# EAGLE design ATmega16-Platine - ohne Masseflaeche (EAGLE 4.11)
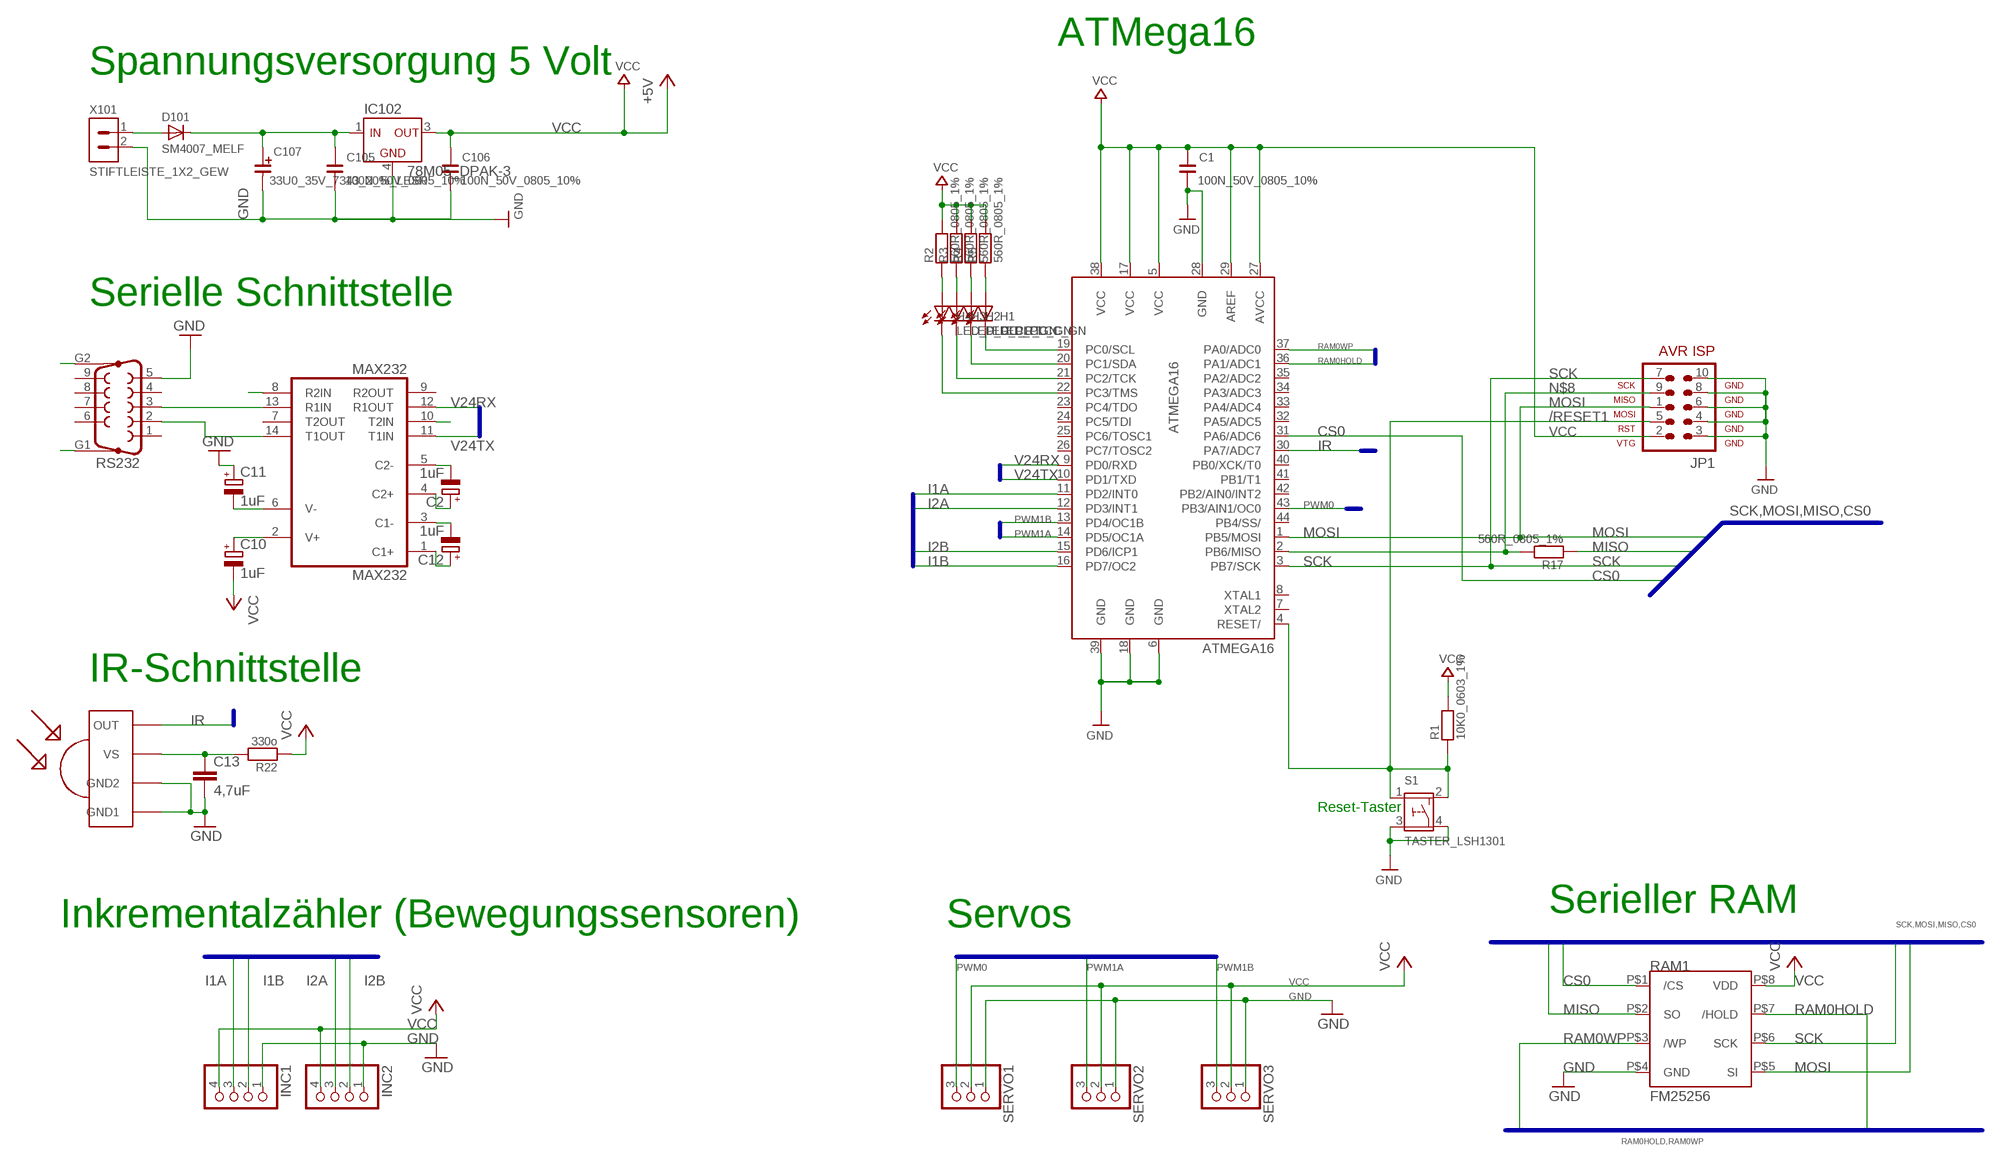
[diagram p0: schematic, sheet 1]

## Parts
ATMEGA16  ATMEGA16  [SQFP-S-10X10-44]
C1  100N_50V_0805_10%  [C0805]
C2  1uF  CPOL-EUE2.5-5  [E2,5-5]
C10  1uF  CPOL-EUE2.5-5  [E2,5-5]
C11  1uF  CPOL-EUE2.5-5  [E2,5-5]
C12  1uF  CPOL-EUE2.5-5  [E2,5-5]
C13  4,7uF  C-EU025-024X044  [C025-024X044]
C105  100N_50V_0805_10%  [C0805]
C106  100N_50V_0805_10%  [C0805]
C107  33U0_35V_7343_20%_LESR  [CT7343]
D101  SM4007_MELF  [MELF]
H1  LED_PLCC_GN  [PLCC2]
H2  LED_PLCC_GN  [PLCC2]
H3  LED_PLCC_GN  [PLCC2]
H4  LED_PLCC_RT  [PLCC2]
IC102  78M05_DPAK-3  [DPAK-3]
INC1  PINHD-1X4  [1X04]
INC2  PINHD-1X4  [1X04]
JP1  AVR-ISP-10  [AVR-ISP-10]
MAX232  MAX232  [DIL16]
R1  10K0_0603_1%  [R0603]
R2  560R_0805_1%  [R0805]
R3  560R_0805_1%  [R0805]
R4  560R_0805_1%  [R0805]
R5  560R_0805_1%  [R0805]
R17  560R_0805_1%  [R0805]
R22  330o  10K0_0603_1%  [R0603]
RAM1  FM25256  [EIAJ-SOIC-8]
RS232  F09HP  [F09HP]
S1  TASTER_LSH1301  [LSH1301]
SERVO1  PINHD-1X3  [1X03]
SERVO2  PINHD-1X3  [1X03]
SERVO3  PINHD-1X3  [1X03]
TSOP6236  TSOP6236  [TSOP62XX]
X101  STIFTLEISTE_1X2_GEW  [PFOSTENSTECKER_1X2_GEW]

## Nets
/RESET1: ATMEGA16.4(RESET/) JP1.5 R1.1 S1.1 S1.2
CS0: ATMEGA16.31(PA6/ADC6) RAM1.P$1(/CS)
GND: ATMEGA16.6(GND) ATMEGA16.18(GND) ATMEGA16.28(GND) ATMEGA16.39(GND) C1.2 C11.+ C13.2 C105.2 C106.2 C107.-(MINUS) IC102.4(GND) INC1.1 INC2.1 JP1.3 JP1.4 JP1.6 JP1.8 JP1.10 MAX232.8(R2IN) MAX232.10(T2IN) RAM1.P$4(GND) RS232.5 RS232.G1 RS232.G2 S1.3 S1.4 SERVO1.1 SERVO2.1 SERVO3.1 TSOP6236.GND1 TSOP6236.GND2 X101.2
I1A: ATMEGA16.11(PD2/INT0) INC1.3
I1B: ATMEGA16.16(PD7/OC2) INC1.2
I2A: ATMEGA16.12(PD3/INT1) INC2.3
I2B: ATMEGA16.15(PD6/ICP1) INC2.2
IR: ATMEGA16.30(PA7/ADC7) TSOP6236.OUT
MISO: R17.1 RAM1.P$2(SO)
MOSI: ATMEGA16.1(PB5/MOSI) JP1.1 RAM1.P$5(SI)
N$8: ATMEGA16.2(PB6/MISO) JP1.9 R17.2
N$9: D101.A X101.1
N$11: H1.A(A1) R5.1
N$12: C105.1 C107.+(PLUS) D101.C IC102.1(IN)
N$13: H2.A(A1) R4.1
N$19: H3.A(A1) R3.1
N$20: H4.A(A1) R2.1
N$21: ATMEGA16.19(PC0/SCL) H1.K
N$22: ATMEGA16.20(PC1/SDA) H2.K
N$23: ATMEGA16.21(PC2/TCK) H3.K
N$24: ATMEGA16.22(PC3/TMS) H4.K
N$29: C2.- MAX232.5(C2-)
N$30: C2.+ MAX232.4(C2+)
N$31: C12.- MAX232.3(C1-)
N$32: C12.+ MAX232.1(C1+)
N$33: C11.- MAX232.6(V-)
N$34: C10.+ MAX232.2(V+)
N$40: MAX232.14(T1OUT) RS232.2
N$41: MAX232.13(R1IN) RS232.3
N$49: C13.1 R22.2 TSOP6236.VS
PWM0: ATMEGA16.43(PB3/AIN1/OC0) SERVO1.3
PWM1A: ATMEGA16.14(PD5/OC1A) SERVO2.3
PWM1B: ATMEGA16.13(PD4/OC1B) SERVO3.3
RAM0HOLD: ATMEGA16.36(PA1/ADC1) RAM1.P$7(/HOLD)
RAM0WP: ATMEGA16.37(PA0/ADC0) RAM1.P$3(/WP)
SCK: ATMEGA16.3(PB7/SCK) JP1.7 RAM1.P$6(SCK)
V24RX: ATMEGA16.9(PD0/RXD) MAX232.12(R1OUT)
V24TX: ATMEGA16.10(PD1/TXD) MAX232.11(T1IN)
VCC: ATMEGA16.5(VCC) ATMEGA16.17(VCC) ATMEGA16.27(AVCC) ATMEGA16.29(AREF) ATMEGA16.38(VCC) C1.1 C10.- C106.1 IC102.3(OUT) INC1.4 INC2.4 JP1.2 R1.2 R2.2 R3.2 R4.2 R5.2 R22.1 RAM1.P$8(VDD) SERVO1.2 SERVO2.2 SERVO3.2 ; supply symbol labelled +5V
Unconnected: ATMEGA16.7(XTAL2) ATMEGA16.8(XTAL1) ATMEGA16.23(PC4/TDO) ATMEGA16.24(PC5/TDI) ATMEGA16.25(PC6/TOSC1) ATMEGA16.26(PC7/TOSC2) ATMEGA16.32(PA5/ADC5) ATMEGA16.33(PA4/ADC4) ATMEGA16.34(PA3/ADC3) ATMEGA16.35(PA2/ADC2) ATMEGA16.40(PB0/XCK/T0) ATMEGA16.41(PB1/T1) ATMEGA16.42(PB2/AIN0/INT2) ATMEGA16.44(PB4/SS/) MAX232.7(T2OUT) MAX232.9(R2OUT) RS232.1 RS232.4 RS232.6 RS232.7 RS232.8 RS232.9

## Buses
SCK,MOSI,MISO,CS0
IR
PWM0,PWM1A,PWM1B
V24RX,V24TX
I1A,I1B,I2A,I2B
RAM0HOLD,RAM0WP

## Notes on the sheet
- ATMega16
- Spannungsversorgung 5 Volt
- Serielle Schnittstelle
- IR-Schnittstelle
- Reset-Taster
- Servos
- Serieller RAM
- Inkrementalzähler (Bewegungssensoren)

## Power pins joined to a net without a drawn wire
GND: MAX232.15(GND)
VCC: MAX232.16(VCC)

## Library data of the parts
ATMEGA16 = IntegrierteSchaltkreise:ATMEGA16: xxxxxxxx
C1 C105 C106 = Kondensatoren:100N_50V_0805_10%: 10100000
C2 C10-C12 = rcl:CPOL-EU: POLARIZED CAPACITOR, European symbol
C13 = rcl:C-EU: CAPACITOR, European symbol
C107 = Kondensatoren:33U0_35V_7343_20%_LESR: 10100525
D101 = Diode:SM4007_MELF: 10300033
H1-H3 = LED:LED_PLCC_GN: 10800036
H4 = LED:LED_PLCC_RT: 10800053
IC102 = IntegrierteSchaltkreise:78M05_DPAK-3: 10500443
INC1 INC2 = pinhead:PINHD-1X4: PIN HEADER
JP1 = atmel_3:AVR-ISP-10: AVR ISP-10 Serial Programming Header
MAX232 = maxim:MAX232: RS232 TRANSEIVER
R1 R22 = Widerstände:10K0_0603_1%: 10000534
R2-R5 R17 = Widerstände:560R_0805_1%: 10000417
RAM1 = ramtron25xx:FM25256
RS232 = con-subd:F09HP: SUB-D
S1 = Schalter_Taster:TASTER_LSH1301: 11100014
SERVO1-SERVO3 = pinhead:PINHD-1X3: PIN HEADER
TSOP6236 = tsop_2:TSOP6236
X101 = Stecker_Klemmen:STIFTLEISTE_1X2_GEW: 20900248

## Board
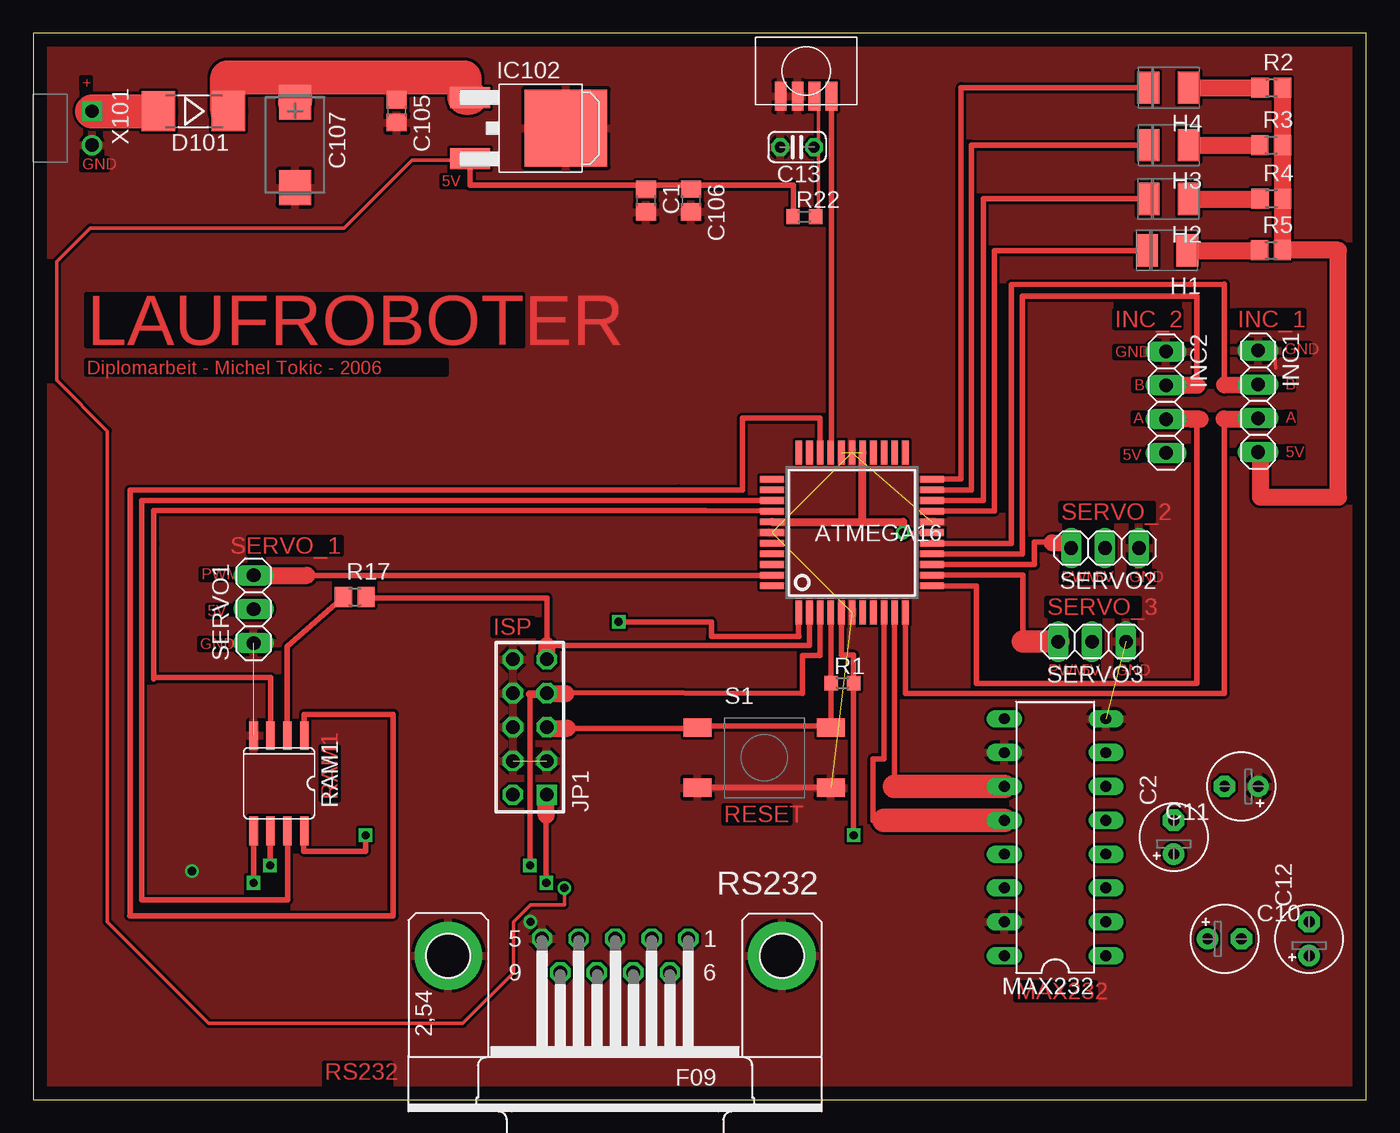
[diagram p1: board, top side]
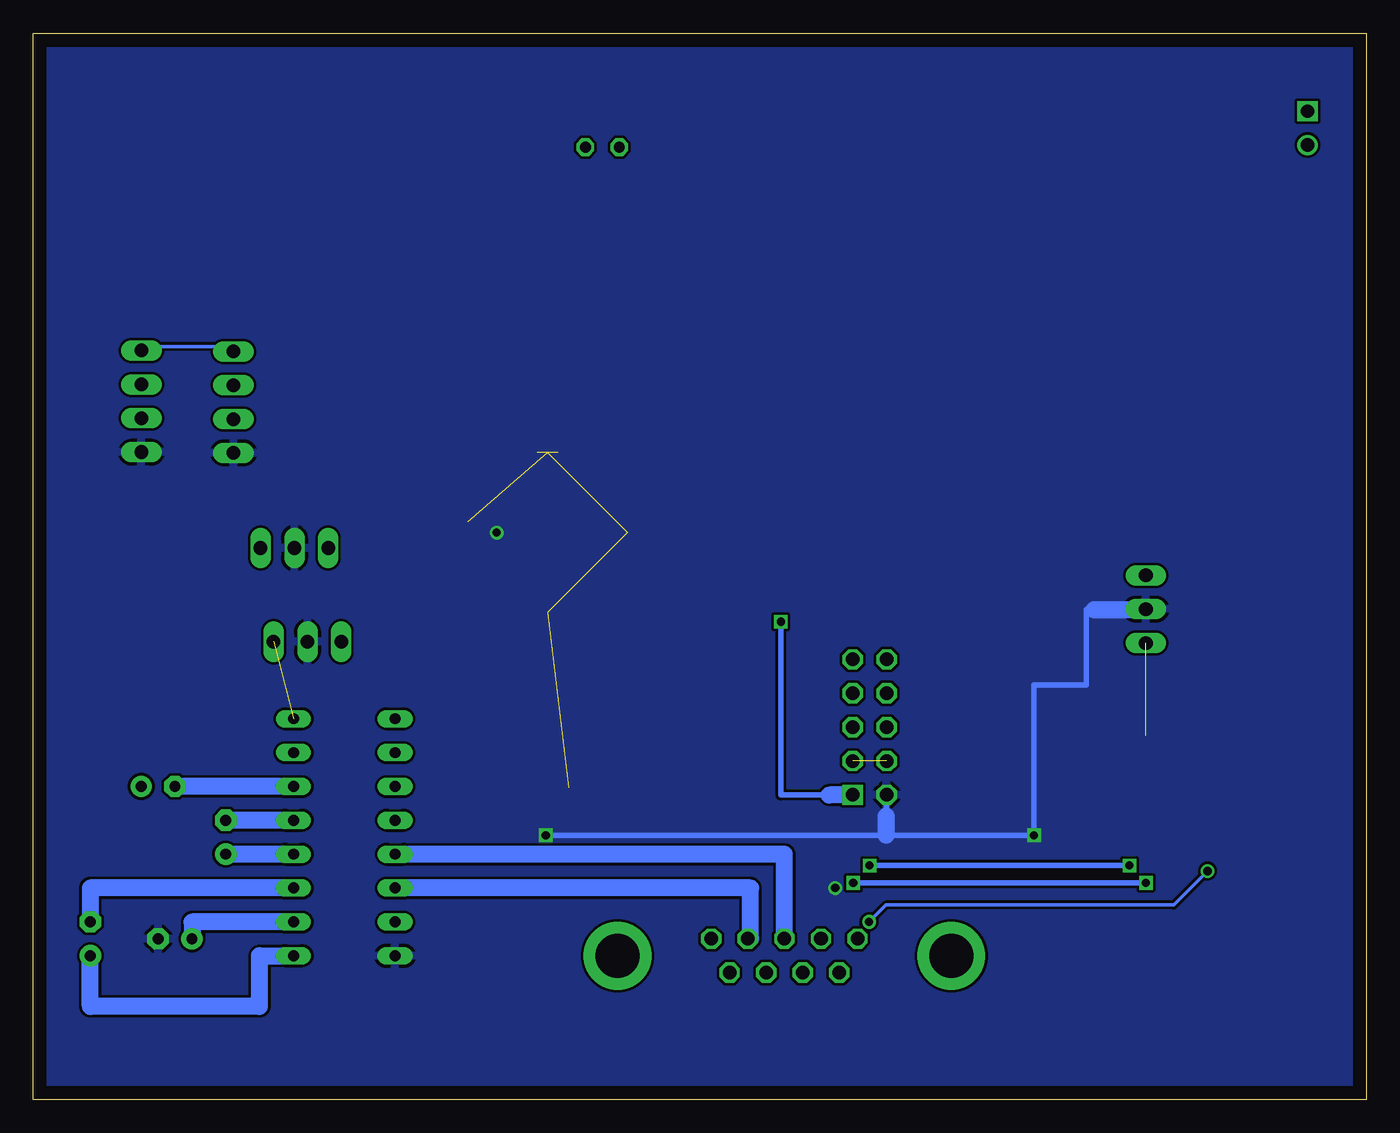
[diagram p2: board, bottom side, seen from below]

Size 100 x 80 mm. Coordinates in mm from the lower left corner, seen from the top.
Outline: 0,0 100,0 100,80 0,80 0,0
Copper layers (1*16): Top 0.035mm / dielectric 1.5mm / Bottom 0.035mm
Design rules "default": minimum track width 10mil, minimum drill 24mil, track to track 8mil, track to pad 8mil, pad to pad 8mil, via to via 8mil, smd to smd 8mil, copper to edge 40mil, drill to drill 8mil, minimum pad ring 10mil, minimum via ring 8mil, stop-mask expansion 4mil, vias tented up to drill 0mil, thermal gap 10mil

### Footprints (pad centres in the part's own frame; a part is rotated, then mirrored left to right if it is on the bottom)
SQFP-S-10X10-44 = smd 0.5 x 1.8: 1 -4,-6; 2 -3.2,-6; 3 -2.4,-6; 4 -1.6,-6; 5 -0.8,-6; 6 0,-6; 7 0.8,-6; 8 1.6,-6; 9 2.4,-6; 10 3.2,-6; 11 4,-6; 23 4,6; 24 3.2,6; 25 2.4,6; 26 1.6,6; 27 0.8,6; 28 0,6; 29 -0.8,6; 30 -1.6,6; 31 -2.4,6; 32 -3.2,6; 33 -4,6 | smd 1.8 x 0.5: 12 6,-4; 13 6,-3.2; 14 6,-2.4; 15 6,-1.6; 16 6,-0.8; 17 6,0; 18 6,0.8; 19 6,1.6; 20 6,2.4; 21 6,3.2; 22 6,4; 34 -6,4; 35 -6,3.2; 36 -6,2.4; 37 -6,1.6; 38 -6,0.8; 39 -6,0; 40 -6,-0.8; 41 -6,-1.6; 42 -6,-2.4; 43 -6,-3.2; 44 -6,-4
C0805 = smd 1.3 x 1.5: 1 -0.85,0; 2 0.85,0
E2,5-5 = drill 0.813 pad 1.6 round: + -1.27,0 | drill 0.813 pad 1.6 octagon: - 1.27,0
C025-024X044 = drill 0.813 octagon: 1 -1.27,0; 2 1.27,0
CT7343 = smd 2.6 x 2.4: + -3.2,0; - 3.2,0
MELF = smd 2.5 x 3: A 2.625,0; C -2.625,0
PLCC2 = smd 1.651 x 2.413: A 1.524,0; K -1.524,0
DPAK-3 = smd 3 x 1.6: 1 -7.18,2.286; 3 -7.18,-2.286 | smd 6.2 x 5.8: 4 0,0
1X04 = drill 1.016 long: 1 -3.81,0; 2 -1.27,0; 3 1.27,0; 4 3.81,0
AVR-ISP-10 = drill 1.016 square: 1 -5.08,-1.27 | drill 1.016 octagon: 2 -5.08,1.27; 3 -2.54,-1.27; 4 -2.54,1.27; 5 0,-1.27; 6 0,1.27; 7 2.54,-1.27; 8 2.54,1.27; 9 5.08,-1.27; 10 5.08,1.27
DIL16 = drill 0.813 long: 1 -8.89,-3.81; 2 -6.35,-3.81; 3 -3.81,-3.81; 4 -1.27,-3.81; 5 1.27,-3.81; 6 3.81,-3.81; 7 6.35,-3.81; 8 8.89,-3.81; 9 8.89,3.81; 10 6.35,3.81; 11 3.81,3.81; 12 1.27,3.81; 13 -1.27,3.81; 14 -3.81,3.81; 15 -6.35,3.81; 16 -8.89,3.81
R0603 = smd 1 x 1.1: 1 -0.85,0; 2 0.85,0
R0805 = smd 1.3 x 1.5: 1 -0.85,0; 2 0.85,0
EIAJ-SOIC-8 = smd 0.65 x 2.15: P$1 -1.905,-3.576; P$2 -0.635,-3.576; P$3 0.635,-3.576; P$4 1.905,-3.576; P$5 1.905,3.576; P$6 0.635,3.576; P$7 -0.635,3.576; P$8 -1.905,3.576
F09HP = drill 1.016 octagon: 1 -5.486,-1.27; 2 -2.743,-1.27; 3 0,-1.27; 4 2.743,-1.27; 5 5.486,-1.27; 6 -4.115,1.27; 7 -1.372,1.27; 8 1.372,1.27; 9 4.115,1.27 | drill 3.302 pad 5.08 round: G1 -12.522,0; G2 12.522,0
LSH1301 = smd 2.1 x 1.4: 1 -5,2.25; 2 5,2.25; 3 -5,-2.25; 4 5,-2.25
1X03 = drill 1.016 long: 1 -2.54,0; 2 0,0; 3 2.54,0
TSOP62XX = smd 0.889 x 2.184: GND1 -8.255,1.905; GND2 -6.985,1.905; OUT -4.445,1.905; VS -5.715,1.905
PFOSTENSTECKER_1X2_GEW = drill 1 square: 1 -1.27,0 | drill 1 round: 2 1.27,0

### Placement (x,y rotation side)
ATMEGA16  61.43,42.54 0 top
C1  45.97,67.45 270 top
C2  85.56,19.68 90 top
C10  89.37,12.06 0 top
C11  90.64,23.49 180 top
C12  95.72,12.06 90 top
C13  57.31,71.46 180 top
C105  27.26,74.16 270 top
C106  49.35,67.46 270 top
C107  19.64,71.62 270 top
D101  12.02,74.16 180 top
H1  85.05,63.71 0 top
H2  85.17,67.57 0 top
H3  85.18,71.61 0 top
H4  85.19,75.92 0 top
IC102  39.96,72.89 0 top
INC1  91.89,52.39 270 top
INC2  84.98,52.32 270 top
JP1  37.25,27.94 90 top
MAX232  76.67,19.68 90 top
R1  60.7,31.25 0 top
R2  92.89,75.92 0 top
R3  92.86,71.61 0 top
R4  92.9,67.61 0 top
R5  92.85,63.71 0 top
R17  24.12,37.7 0 top
R22  57.84,66.24 0 top
RAM1  18.43,23.73 180 top
RS232  43.65,10.79 180 top
S1  54.84,25.65 0 top
SERVO1  16.53,36.79 90 top
SERVO2  80.41,41.38 180 top
SERVO3  79.43,34.36 180 top
TSOP6236  64.33,73.37 0 top
X101  4.4,72.89 270 top

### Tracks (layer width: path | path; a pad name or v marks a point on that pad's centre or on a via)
/RESET1
  Top 0.406: ATMEGA16.4 59.83,31.25 R1.1 59.85,28.38 59.84,28.37 | 59.84,28.37 59.81,28.34 | 59.84,28.03 S1.2 | 59.84,28.03 59.84,28.37 | 38.48,27.9 38.46,27.9 | JP1.5 38.48,27.9 | 38.48,27.9 38.48,27.86 | 40.07,27.86 40.07,27.84 49.84,27.86 S1.1 49.84,28.03 59.84,28.03
  Top 1.27: 38.48,27.86 40.07,27.86
CS0
  Top 0.406: RAM1.P$1 20.33,28.89 26.99,28.89 26.99,13.79 7.21,13.79 7.26,13.83 7.26,45.72 48.44,45.73 53.2,45.73 53.2,51.12 59.02,51.12 ATMEGA16.31 | ATMEGA16.31 59.02,48.43 | ATMEGA16.31
GND  (via drill 0.61)  (7 unrouted)
  Top 0.254: INC1.1 93.18,56.51 93.18,55.24 93.22,54.89
  Top 0.406: S1.4 59.84,23.42 49.84,23.42 S1.3
  Bottom 0.254: INC1.1 90.64,56.51 85.56,56.51 INC2.1 | v37.3,13.33 36.03,14.6 14.44,14.6 v11.9,17.14
  pour Top: 0.47,79.64 99.48,79.64 99.48,0.41 0.58,0.41 0.58,79.31
I1A
  Top 0.406: ATMEGA16.11 65.44,30.46 89.35,30.46 89.35,51.07 | 92,51.08 92,51.07 INC1.3
  Top 1.27: 89.35,51.07 92,51.07
I1B
  Top 0.406: 89.37,53.61 89.37,61.17 73.37,61.14 73.37,43.39 73.4,43.39 73.4,41.73 67.16,41.73 67.16,41.74 | 67.16,41.74 67.16,41.78 | ATMEGA16.16 67.16,41.74
  Top 1.27: 89.37,53.61 INC1.2
I2A
  Top 0.406: ATMEGA16.12 70.77,38.54 70.77,31.22 87.28,31.22 87.28,51.04 | 86.91,51.04 87.52,51.05
  Top 1.27: 87.52,51.05 INC2.3 | 87.28,51.04 86.91,51.04
I2B
  Top 0.406: ATMEGA16.15 74.22,40.94 74.22,42.6 74.21,42.6 74.21,60.28 87.3,60.29 87.3,53.58 | 85.83,53.74 INC2.2
  Top 1.27: 85.83,53.69 85.83,53.74 85.91,53.58 87.3,53.58
IR
  Top 0.406: ATMEGA16.30 59.8,48.54 59.79,48.56 59.89,48.66 TSOP6236.OUT
MISO
  Top 0.406: 19.05,27.28 | RAM1.P$2 19.05,27.28 | R17.1 19.05,34.01 19.05,27.28
MOSI  (via drill 0.61)
  Top 0.406: RAM1.P$5 v16.52,16.26 | JP1.1 38.54,22.85 | JP1.1 | v38.49,16.26 38.48,21.33 | 38.48,22.85 JP1.1 | v43.92,35.85 50.87,35.85 50.87,34.73 57.45,34.73 57.41,34.77 57.41,36.52 ATMEGA16.1
  Top 1.27: 38.48,21.33 38.48,22.85
  Bottom 0.406: v16.52,16.26 v38.49,16.26 | JP1.1 | 40.28,22.85 40.28,22.86 43.92,22.85 v43.92,35.85
  Bottom 1.27: JP1.1 40.28,22.85
N$8
  Top 0.406: R17.2 24.92,37.65 38.54,37.65 38.54,33.03 38.53,33.03 JP1.9 | 38.53,34.07 58.24,34.07 ATMEGA16.2
  Top 1.27: JP1.9 38.53,34.07
N$9
  Top 2.54: 8.21,74.16 X101.1 D101.A
N$11
  Top 1.27: 91.78,63.72 | 91.78,63.72 R5.1 | H1.A 91.78,63.71 91.78,63.72
N$12
  Top 1.27: 27.26,76.7 C105.1
  Top 2.54: D101.C 14.56,74.16 14.56,76.7 19.64,76.7 | 19.64,76.7 19.64,75.43 | 19.64,76.7 C107.+ | IC102.1 32.34,75.17 32.34,76.7 27.26,76.7 19.64,76.7
N$13
  Top 1.27: R4.1 92.04,67.57 H2.A
N$19
  Top 1.27: R3.1 91.89,71.61 H3.A
N$20
  Top 1.27: 91.85,75.92 91.85,75.91 R2.1 | H4.A 91.85,75.92 | 91.85,75.92 91.85,75.93
N$21
  Top 0.406: ATMEGA16.19 72.1,44.14 72.1,63.68 83.29,63.68 83.29,63.71 | 83.29,63.71 83.29,63.72 | 83.29,63.71 H1.K
N$22
  Top 0.406: ATMEGA16.20 71.27,44.94 71.27,67.59 83.48,67.59 83.48,67.57 | 83.48,67.57 83.48,67.52 | 83.48,67.57 H2.K
N$23
  Top 0.406: ATMEGA16.21 70.36,45.74 70.36,71.61 83.44,71.61 | 83.44,71.61 | 83.44,71.61 H3.K
N$24
  Top 0.406: ATMEGA16.22 69.61,46.54 69.61,75.93 83.44,75.93 83.44,75.92 H4.K
N$29
  Bottom 1.27: MAX232.5 C2.-
N$30
  Bottom 1.27: MAX232.4 C2.+
N$31
  Bottom 1.27: MAX232.3 95.72,15.87 C12.-
N$32
  Bottom 1.27: MAX232.1 83.02,10.79 83.02,6.98 95.72,6.98 C12.+
N$33
  Bottom 1.27: MAX232.6 C11.-
N$34
  Bottom 1.27: MAX232.2 88.1,13.33 C10.+
N$40
  Bottom 1.27: MAX232.14 46.19,15.87 46.19,12.06 RS232.2
N$41
  Bottom 1.27: MAX232.13 43.65,18.41 RS232.3
N$49
  Top 0.254: 58.89,71.75 58.89,66.67 R22.2 | 58.89,71.75 58.89,74.29 TSOP6236.VS | 58.89,71.75 C13.1
PWM0
  Top 0.406: 55.3,39.33 55.31,39.34 ATMEGA16.43 | 55.3,39.33 | 55.3,39.33 55.22,39.33 55.21,39.34 55.2,39.33 20.54,39.33
  Top 1.27: SERVO1.3 20.54,39.33
PWM1A
  Top 0.254: SERVO2.3 77.94,41.27 77.94,41.78
  Top 0.406: ATMEGA16.14 75.12,40.14 75.12,41.82 75.11,41.82 75.12,41.83 76.39,41.84 76.44,41.76
  Top 1.27: 76.44,41.76 77.94,41.78 77.99,41.78
PWM1B
  Top 0.406: ATMEGA16.13 74.23,39.34 74.23,34.36
  Top 1.676: 74.23,34.36 SERVO3.3
RAM0HOLD
  Top 0.406: RAM1.P$7 19.09,20.13 19.09,14.99 8.12,14.99 8.12,44.94 49.39,44.94 49.28,44.94 55.21,44.94 | 55.21,44.94 55.21,44.99 | 55.21,44.94 ATMEGA16.36
RAM0WP
  Top 0.406: RAM1.P$3 17.81,27.31 17.81,31.67 9.05,31.67 | 9.05,31.67 9.02,31.67 | ATMEGA16.37 55.46,44.17 50.45,44.2 50.45,44.21 9.05,44.21 9.05,41.66 | 9.05,31.67 9.05,31.55 | 9.05,31.67 9.05,41.66 | 9.05,41.66 9.05,41.82
SCK  (via drill 0.61)
  Top 0.406: RAM1.P$6 17.77,20.12 v17.77,17.56 | v37.26,17.56 37.26,17.84 37.26,30.43 | JP1.7 38.58,30.43 38.66,30.43 38.7,30.47 | 39.96,30.47 39.96,30.54 57.7,30.47 57.7,33.32 59.02,33.32 ATMEGA16.3 | ATMEGA16.3 59.02,36.59 | ATMEGA16.3
  Top 0.61: 37.26,30.43 38.58,30.43
  Top 1.27: 38.7,30.47 39.96,30.47
  Bottom 0.406: v17.77,17.56 v37.26,17.56
V24RX
  Top 0.406: ATMEGA16.9 63.81,36.54 63.82,26.2 63.82,25.57 63,25.57 63,20.95 63.81,20.95
  Top 1.778: 63.81,20.95 MAX232.12
V24TX
  Top 0.406: ATMEGA16.10 64.6,36.54 64.6,23.49
  Top 1.778: 64.6,23.49 MAX232.11
VCC  (via drill 0.61)  (1 unrouted)
  Top 0.254: v65.24,42.54 ATMEGA16.17 67.78,42.54 | C1.1 46.19,67.94 46.19,68.61 | 48.73,68.61 48.73,67.94 C106.1 | v39.84,15.87 39.84,14.6 37.3,14.6 36.03,13.33 36.03,9.52 32.22,5.71 13.17,5.71 5.55,13.33 5.55,50.16 1.74,53.97 1.74,62.86 4.28,65.4 23.33,65.4 28.41,70.48 32.22,70.48 IC102.3
  Top 0.406: ATMEGA16.5 60.63,33.35 60.62,33.34 61.53,33.34 61.55,33.32 R1.2 61.55,31.13 v61.55,19.83 | RAM1.P$8 20.29,20.1 20.29,18.63 24.92,18.63 v24.92,19.83 | R22.1 57.01,66.24 57.01,68.61 48.73,68.61 46.19,68.61 32.77,68.61 | 32.77,68.61 32.76,68.61 | 32.77,68.61 32.77,68.6 | IC102.3 32.77,70.6 32.77,68.61
  Top 0.61: 65.26,42.54 65.26,42.47 | 65.26,42.54 v65.24,42.54 | ATMEGA16.38 62.21,43.34 | 62.21,43.34 65.26,43.34 65.26,42.54 | ATMEGA16.27 62.21,48.54 62.21,43.34
  Top 1.27: 93.73,71.61 93.73,71.57 | R2.2 93.73,71.61 | 93.73,67.61 93.73,67.55 | 93.73,71.61 R3.2 | 93.73,67.61 93.73,71.61 | 93.73,67.61 R4.2 | 93.73,67.61 93.73,63.72 R5.2 97.92,63.72 97.92,45.2 92.06,45.2 92.06,45.31 92.04,48.53 INC1.4
  Bottom 0.406: 36.02,19.83 v24.92,19.83 24.92,20.12 | 36.02,19.83 | 36.02,19.83 36.06,19.83 36.06,19.81 61.55,19.81 v61.55,19.83 | 24.92,20.12 24.92,31.09 20.99,31.09 20.99,36.76 20.42,36.76 | 24.92,20.12 24.97,20.12 | 36.02,19.83 | 17.52,36.86 16.53,36.76 SERVO1.2 | 36.02,19.83 36.02,19.86 35.99,19.86 35.98,19.86 | 35.99,21.28 JP1.2
  Bottom 1.27: 20.42,36.76 16.53,36.76 | 35.99,19.86 35.99,21.28
  pour Bottom: 0.58,79.31 0.58,0.63 99.37,0.63 99.37,79.42 0.47,79.42 0.47,78.98

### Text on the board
Top: + | GND | 5V | INC_2 | INC_1 | LAUFROBOTER | GND | GND | Diplomarbeit - Michel Tokic - 2006 | B | B | A | A | 5V | 5V | SERVO_2 | SERVO_1 | PWM | PWM | 5V | GND | 5V | SERVO_3 | ISP | GND | PWM | 5V | GND | RAM1 | RESET | MAX232 | RS232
